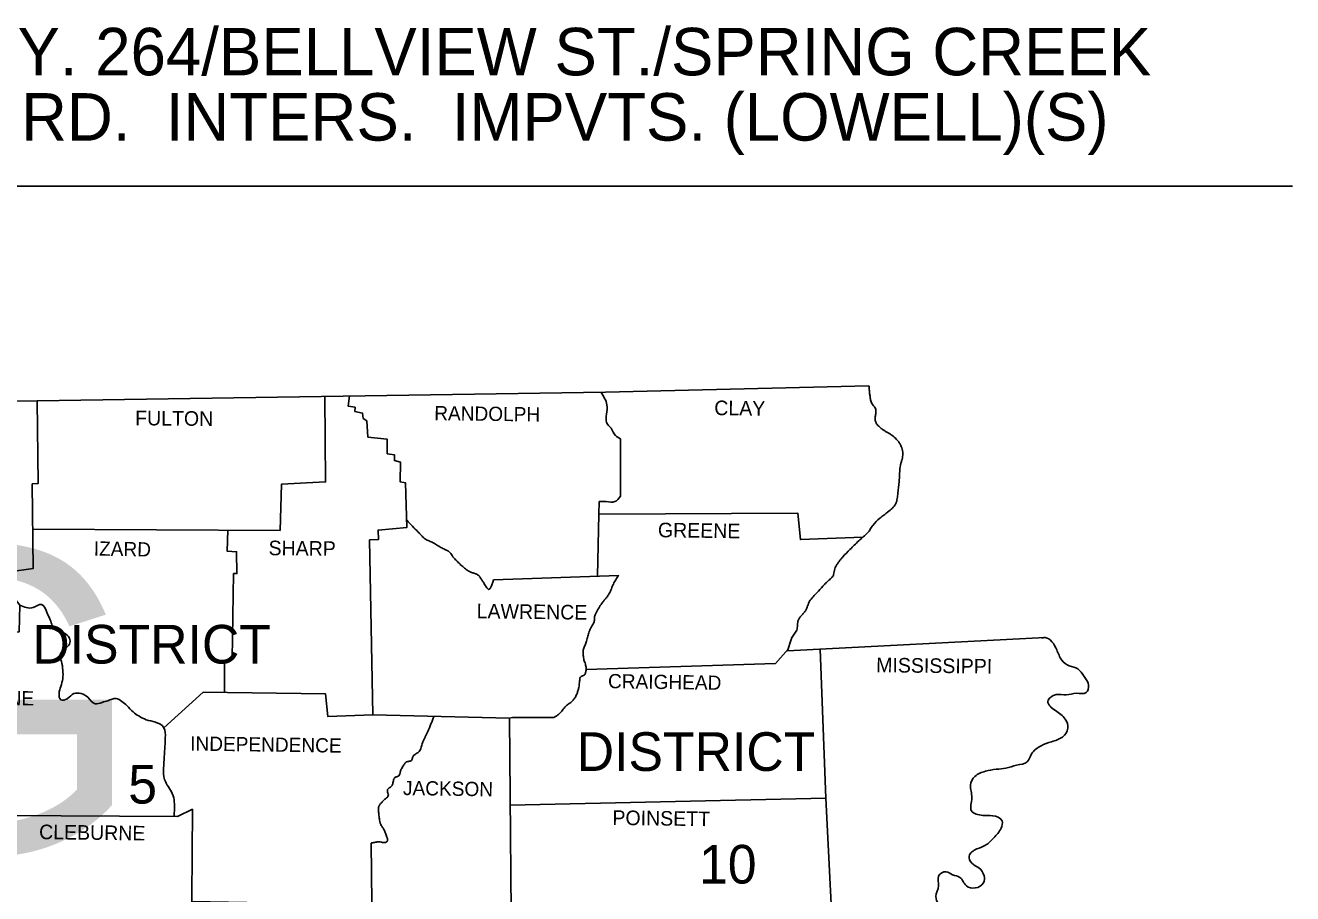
# Model space of a CAD drawing. Extents: x 670147 to 673275, y 705573 to 707613.
# Drawn here: x 672901.2 to 673274.6, y 707276.6 to 707532.5 of the extents above; entities that cross this region are included whole.
import ezdxf

# ---------------------------------------------------------------- set-up
doc = ezdxf.new("R2010")
doc.units = 0
for name, color, linetype in [('2', 7, 'Continuous'), ('Default', 7, 'Continuous'), ('Level 1', 7, 'Continuous'), ('R_Border', 7, 'Continuous')]:
    doc.layers.add(name, color=color, linetype=linetype)

msp = doc.modelspace()

# ---------------------------------------------------------------- linework, layer by layer
at = {"layer": '2'}
for p, q in [((673070.18, 707388.43), (673070.27, 707392.13)), ((673125.77, 707348.13), (673126.85, 707351.45))]:
    msp.add_line(p, q, dxfattribs=at)
for points in [[(672601.17, 707421.63), (672762.87, 707421.53), (672904.77, 707421.83), (673072.17, 707424.43), (673149.77, 707426.23)], [(672904.77, 707421.83), (672904.97, 707397.43), (672903.27, 707397.33), (672903.57, 707372.43), (672896.57, 707371.43), (672897.17, 707364.73), (672899.57, 707361.63), (672899.37, 707353.73), (672885.77, 707353.23), (672885.27, 707341.03), (672872.87, 707340.63), (672872.27, 707325.83), (672872.97, 707324.63), (672873.27, 707301.03), (672894.67, 707299.63), (672894.37, 707246.93), (672911.37, 707246.43), (672911.37, 707192.83), (672897.97, 707191.83), (672896.97, 707180.03), (672874.47, 707179.93)], [(672989.47, 707423.14), (672989.67, 707397.93), (672976.67, 707397.23), (672976.27, 707383.63), (672903.43, 707384.03)], [(672996.75, 707423.26), (672996.37, 707420.23), (672998.37, 707419.93), (672998.27, 707418.73), (673000.57, 707418.23), (673000.77, 707416.63), (673001.87, 707415.93), (673002.17, 707411.13), (673007.87, 707410.53), (673007.87, 707406.23), (673009.97, 707405.93), (673009.97, 707404.23), (673011.77, 707403.73), (673011.67, 707397.93), (673013.27, 707397.63), (673013.67, 707384.53), (673005.17, 707383.73), (673005.27, 707380.93), (673002.67, 707380.83), (673003.57, 707329.23), (673043.87, 707328.33), (673044.57, 707248.13), (673018.27, 707247.43), (673017.75, 707261.53)], [(673076.57, 707410.63), (673076.57, 707393.73)], [(673069.75, 707370.1), (673070.18, 707388.43), (673070.27, 707388.43), (673128.77, 707388.73), (673129.57, 707380.93), (673147.92, 707381.6)], [(672960.89, 707383.71), (672960.67, 707377.53), (672963.47, 707377.33), (672963.57, 707370.93), (672962.57, 707370.93), (672962.17, 707345.73), (672959.87, 707344.73), (672959.87, 707335.84)], [(673039.17, 707369.03), (673076.04, 707370.32)], [(673125.77, 707348.13), (673201.67, 707352.03)], [(673066.43, 707342.62), (673122.27, 707344.43), (673125.94, 707348.66)], [(673135.35, 707348.62), (673137.07, 707304.73), (673139.11, 707263.77)], [(672942.07, 707325.44), (672953.67, 707335.93), (672989.67, 707335.43), (672990.37, 707328.73), (673003.57, 707329.23)], [(673056.97, 707328.53), (673044.77, 707328.53), (673043.87, 707328.33)], [(673137.07, 707304.73), (673044.1, 707302.61)], [(672894.67, 707299.63), (672946.07, 707299.33), (672950.47, 707301.43), (672950.17, 707262.33), (672947.17, 707261.03), (672944.47, 707258.73), (672943.57, 707257.83), (672943.47, 707246.63), (672904.57, 707246.63)], [(673003.07, 707291.43), (673003.27, 707273.83), (672977.27, 707273.73), (672950.26, 707274.24)]]:
    msp.add_lwpolyline(points, dxfattribs=at)
for points in [[(673149.77, 707426.23), (673149.86, 707425.12), (673149.97, 707424.02), (673150.11, 707422.92), (673150.27, 707421.83), (673150.51, 707421.21), (673150.91, 707420.65), (673151.35, 707420.1), (673151.67, 707419.53), (673151.8, 707418.51), (673151.67, 707417.42), (673151.6, 707416.33), (673151.67, 707415.81), (673151.87, 707415.33), (673152.63, 707414.35), (673153.57, 707413.53), (673154.29, 707413.05), (673155.03, 707412.63), (673155.76, 707412.21), (673156.47, 707411.73), (673157.91, 707410.45), (673158.53, 707409.7), (673158.81, 707409.28), (673159.07, 707408.83), (673159.43, 707407.98), (673159.65, 707407.13), (673159.72, 707406.28), (673159.67, 707405.43), (673159.5, 707404.56), (673159.25, 707403.69), (673159.02, 707402.81), (673158.87, 707401.93), (673158.82, 707400.96), (673158.78, 707399.98), (673158.74, 707399), (673158.67, 707398.03), (673158.27, 707394.63), (673158.08, 707393.06), (673157.93, 707392.29), (673157.82, 707391.91), (673157.67, 707391.53), (673156.63, 707390.14), (673155.27, 707389.03), (673154.7, 707388.57), (673154.12, 707388.13), (673153.54, 707387.69), (673152.97, 707387.23), (673150.87, 707385.13), (673150.48, 707384.59), (673150.14, 707384.01), (673149.79, 707383.44), (673149.37, 707382.93), (673146.77, 707380.53), (673144.17, 707378.03), (673142.07, 707375.83), (673141.5, 707375.17), (673140.96, 707374.47), (673140.46, 707373.76), (673139.97, 707373.03), (673139.67, 707372.28), (673139.52, 707371.45), (673139.35, 707370.63), (673139.2, 707370.26), (673138.97, 707369.93), (673138.42, 707369.36), (673137.83, 707368.82), (673137.23, 707368.29), (673136.67, 707367.73), (673134.87, 707365.73), (673132.47, 707363.03), (673132.08, 707362.41), (673131.81, 707361.72), (673131.57, 707361.01), (673131.27, 707360.33), (673130.74, 707359.54), (673130.11, 707358.79), (673129.49, 707358.04), (673128.97, 707357.23), (673128.76, 707356.51), (673128.7, 707355.74), (673128.65, 707354.96), (673128.47, 707354.23), (673128.15, 707353.61), (673127.75, 707353.02), (673127.34, 707352.43), (673126.97, 707351.83), (673126.85, 707351.45)], [(673070.76, 707424.41), (673072.57, 707420.63), (673072.47, 707417.93), (673072.47, 707415.43), (673073.77, 707413.73), (673075.07, 707411.63), (673076.57, 707410.63)], [(673076.57, 707393.73), (673074.87, 707392.13), (673072.37, 707392.13), (673070.27, 707392.13)], [(673013.61, 707386.63), (673015.28, 707384.87), (673016.97, 707383.13), (673017.21, 707382.89), (673017.9, 707382.16), (673018.37, 707381.68), (673018.62, 707381.45), (673018.74, 707381.34), (673018.87, 707381.23), (673019.38, 707380.89), (673019.94, 707380.63), (673020.52, 707380.4), (673021.07, 707380.13), (673022.37, 707379.38), (673023.67, 707378.63), (673024.25, 707378.33), (673024.83, 707378.05), (673025.7, 707377.6), (673025.84, 707377.52), (673025.97, 707377.43), (673026.41, 707377.02), (673026.77, 707376.53), (673027.1, 707376.01), (673027.28, 707375.76), (673027.47, 707375.53), (673028.51, 707374.47), (673029.57, 707373.43), (673030.08, 707372.98), (673030.6, 707372.55), (673031.13, 707372.14), (673031.67, 707371.73), (673032.49, 707371.31), (673033.4, 707371.02), (673034.27, 707370.69), (673034.65, 707370.45), (673034.82, 707370.3), (673034.97, 707370.13), (673035.27, 707369.72), (673035.54, 707369.29), (673035.8, 707368.86), (673036.07, 707368.43), (673036.26, 707368.15), (673036.45, 707367.86), (673036.82, 707367.28), (673037.2, 707366.74), (673037.39, 707366.52), (673037.48, 707366.42), (673037.53, 707366.37), (673037.57, 707366.33), (673037.69, 707366.26), (673037.8, 707366.25), (673038.02, 707366.38), (673038.46, 707367.09), (673038.85, 707368.1), (673039.02, 707368.6), (673039.17, 707369.03)], [(673076.04, 707370.32), (673075.2, 707369.11), (673074.47, 707367.83), (673074.16, 707367.13), (673073.89, 707366.42), (673073.62, 707365.71), (673073.27, 707365.03), (673072.71, 707364.2), (673072.1, 707363.42), (673071.47, 707362.64), (673070.87, 707361.83), (673069.91, 707360.32), (673069.47, 707359.54), (673069.07, 707358.73), (673068.94, 707358.22), (673068.91, 707357.68), (673068.88, 707357.14), (673068.77, 707356.63), (673068.45, 707355.92), (673068.06, 707355.24), (673067.68, 707354.55), (673067.37, 707353.83), (673067.16, 707353.13), (673066.97, 707352.43), (673066.78, 707351.73), (673066.57, 707351.03), (673066.36, 707350.43), (673066.11, 707349.83), (673065.88, 707349.24), (673065.67, 707348.63), (673065.56, 707348.02), (673065.55, 707347.38), (673065.59, 707346.75), (673065.67, 707346.13), (673065.81, 707345.5), (673066.01, 707344.88), (673066.22, 707344.25), (673066.37, 707343.63), (673066.43, 707343.06), (673066.42, 707342.48), (673066.33, 707341.9), (673066.26, 707341.61), (673066.17, 707341.33), (673065.87, 707340.99), (673065.4, 707340.78), (673064.94, 707340.57), (673064.67, 707340.23), (673064.59, 707339.88), (673064.54, 707339.51), (673064.47, 707338.78), (673064.4, 707338.05), (673064.27, 707337.33), (673064.01, 707336.32), (673063.67, 707335.33), (673063.12, 707334.27), (673062.77, 707333.78), (673062.37, 707333.33), (673061.92, 707332.92), (673061.42, 707332.57), (673060.93, 707332.22), (673060.47, 707331.83), (673059.96, 707331.28), (673059.48, 707330.68), (673059, 707330.09), (673058.47, 707329.53), (673057.77, 707328.98), (673057.39, 707328.74), (673056.97, 707328.53)], [(672899.57, 707361.63), (672903.57, 707360.93), (672905.97, 707361.83), (672907.67, 707359.23), (672908.57, 707357.23), (672910.07, 707354.33), (672912.47, 707353.43), (672914.27, 707351.83), (672914.27, 707350.13), (672912.67, 707348.53), (672911.47, 707346.93), (672911.87, 707345.03), (672912.27, 707342.43), (672912.27, 707339.93), (672911.67, 707337.63), (672911.17, 707335.53), (672911.67, 707333.73), (672913.57, 707334.03), (672915.57, 707335.53), (672917.67, 707335.53), (672919.67, 707334.43), (672921.77, 707332.53), (672923.87, 707332.93), (672925.57, 707333.43), (672927.97, 707334.13), (672929.67, 707333.23), (672931.17, 707332.03), (672932.97, 707330.13), (672934.67, 707328.93), (672936.87, 707327.83), (672939.57, 707327.13), (672942.07, 707325.43), (672942.47, 707322.53), (672942.37, 707320.03), (672942.17, 707316.93), (672941.97, 707313.53), (672942.27, 707310.23), (672943.37, 707308.03), (672944.77, 707305.43), (672945.17, 707303.03), (672945.07, 707299.23)], [(673200.57, 707351.93), (673201.67, 707352.03), (673205.07, 707348.43), (673206.57, 707345.43), (673208.77, 707343.73), (673211.27, 707342.83), (673213.17, 707340.53), (673214.47, 707338.03), (673213.77, 707335.83), (673210.97, 707335.63), (673207.87, 707335.13), (673204.87, 707335.23), (673202.47, 707333.23), (673204.67, 707330.53), (673207.57, 707328.03), (673208.37, 707325.33), (673206.77, 707322.73), (673203.57, 707321.33), (673200.47, 707320.13), (673197.67, 707317.73), (673196.37, 707315.43), (673193.27, 707314.43), (673190.07, 707313.53), (673187.27, 707313.23), (673184.07, 707312.63), (673180.97, 707311.13), (673179.67, 707308.53), (673180.07, 707304.83), (673179.97, 707300.93), (673183.27, 707299.63), (673186.17, 707299.53), (673188.97, 707298.03), (673188.67, 707295.83), (673186.57, 707293.03), (673184.07, 707290.83), (673181.57, 707289.73), (673179.27, 707287.63), (673180.07, 707285.53), (673182.17, 707284.13), (673183.67, 707281.83), (673183.47, 707279.73), (673181.07, 707278.23), (673178.47, 707278.83), (673176.57, 707281.33), (673174.37, 707282.13), (673172.47, 707283.03), (673170.27, 707281.73), (673170.27, 707278.83), (673169.47, 707275.73), (673170.17, 707273.43), (673171.07, 707270.23), (673170.97, 707267.83), (673170.17, 707264.43), (673168.47, 707260.93), (673166.47, 707259.83), (673165.67, 707263.63), (673165.27, 707266.73), (673164.07, 707268.53), (673162.47, 707268.63), (673160.37, 707267.13), (673158.07, 707264.83), (673155.17, 707262.33), (673153.47, 707259.83), (673154.37, 707256.73), (673156.57, 707255.93), (673158.27, 707256.53), (673159.17, 707258.53), (673160.87, 707258.83), (673162.47, 707255.73)], [(673021.64, 707328.83), (673020.74, 707326.57), (673019.77, 707324.33), (673019.43, 707323.58), (673019.07, 707322.83), (673018.72, 707322.08), (673018.37, 707321.33), (673018.13, 707320.69), (673017.92, 707320.03), (673017.72, 707319.37), (673017.47, 707318.73), (673017.1, 707318.27), (673016.58, 707317.93), (673016.03, 707317.61), (673015.78, 707317.43), (673015.57, 707317.23), (673015.4, 707316.91), (673015.28, 707316.53), (673015.17, 707316.15), (673014.97, 707315.83), (673014.59, 707315.62), (673014.12, 707315.54), (673013.65, 707315.46), (673013.27, 707315.23), (673013.08, 707315), (673012.9, 707314.76), (673012.56, 707314.27), (673012.25, 707313.76), (673011.97, 707313.23), (673011.8, 707312.79), (673011.68, 707312.32), (673011.55, 707311.86), (673011.37, 707311.43), (673011.09, 707311.17), (673010.69, 707311.02), (673010.28, 707310.87), (673009.97, 707310.63), (673009.84, 707310.39), (673009.74, 707310.12), (673009.6, 707309.53), (673009.48, 707308.95), (673009.34, 707308.55), (673009.27, 707308.43), (673008.99, 707308.12), (673008.62, 707307.84), (673008.25, 707307.56), (673007.97, 707307.23), (673007.92, 707306.76), (673008.06, 707306.22), (673008.19, 707305.68), (673008.07, 707305.23), (673007.99, 707305.13), (673007.91, 707305.04), (673007.33, 707304.53), (673006.94, 707304.19), (673006.57, 707303.83), (673006.23, 707303.46), (673005.89, 707303.09), (673005.59, 707302.69), (673005.47, 707302.47), (673005.37, 707302.23), (673005.25, 707301.14), (673005.37, 707300.03), (673005.45, 707299.3), (673005.53, 707298.57), (673005.66, 707297.85), (673005.75, 707297.49), (673005.87, 707297.13), (673006.09, 707296.68), (673006.35, 707296.27), (673006.62, 707295.86), (673006.87, 707295.43), (673007.36, 707294.34), (673007.57, 707293.79), (673007.77, 707293.23), (673007.88, 707292.88), (673007.95, 707292.5), (673007.9, 707292.13), (673007.81, 707291.97), (673007.75, 707291.9), (673007.67, 707291.83), (673007.06, 707291.6), (673006.43, 707291.66), (673005.8, 707291.81), (673005.48, 707291.85), (673005.17, 707291.83), (673004.65, 707291.74), (673004.12, 707291.66), (673003.6, 707291.55), (673003.07, 707291.43)]]:
    msp.add_spline(points, degree=3, dxfattribs=at)
at = {"layer": 'Level 1'}
msp.add_line((673274.58, 707485.12), (672843.58, 707485.12), dxfattribs=at)

# ---------------------------------------------------------------- texts
at = {"layer": '2'}
for s, height, rotation, p in [('CLAY', 4.299, 359.2258, (673104.17, 707417.63)), ('FULTON', 4.299, 359.4996, (672933.57, 707414.63)), ('RANDOLPH', 4.2, 359.2584, (673021.67, 707416.13)), ('GREENE', 4.301, 359.2361, (673087.57, 707381.63)), ('IZARD', 4.199, 358.9259, (672921.37, 707376.23)), ('SHARP', 4.299, 359.3905, (672972.87, 707376.33)), ('LAWRENCE', 4.301, 359.2678, (673034.17, 707357.73)), ('MISSISSIPPI', 4.2994, 359.3097, (673151.87, 707341.83)), ('CRAIGHEAD', 4.2, 359.1159, (673072.87, 707337.13)), ('STONE', 4.199, 359.4001, (672884.47, 707332.23)), ('INDEPENDENCE', 4.1992, 359.2188, (672949.77, 707318.73)), ('JACKSON', 4.199, 359.1352, (673012.47, 707305.63)), ('POINSETT', 4.299, 359.1987, (673074.17, 707296.83)), ('CLEBURNE', 4.299, 359.2535, (672905.27, 707292.63))]:
    msp.add_text(s, height=height, rotation=rotation, dxfattribs=at).set_placement(p)
for s, p in [('DISTRICT', (672903.29, 707344.38)), ('DISTRICT', (673063.67, 707312.73)), ('5', (672931.56, 707303.1)), ('10', (673099.7, 707279.53))]:
    msp.add_text(s, height=11.4, dxfattribs=at).set_placement(p)
at = {"layer": 'Default'}
msp.add_text('HWY.  264 BELLVIEW ST.   SPRING ', height=89.9998, dxfattribs=at).set_placement((670936.05, 707288.67))
at = {"layer": 'R_Border'}
for s, p in [('HWY. 264/BELLVIEW ST./SPRING CREEK ', (672867.75, 707517.78)), ('RD.  INTERS.  IMPVTS. (LOWELL)(S)', (672899.97, 707498.53))]:
    msp.add_text(s, height=14, dxfattribs=at).set_placement(p)

doc.saveas('drawing.dxf')
